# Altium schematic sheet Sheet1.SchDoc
size 431 x 279 mm; Date: Not shown in title block; ApprovedBy: Not shown in title block; CheckedBy: Not shown in title block; Author: Not shown in title block; CompanyName: Not shown in title block; Engineer: Not shown in title block; Organization: Not shown in title block; Address1: Not shown in title block; Address2: Not shown in title block; Address3: Not shown in title block; Address4: Not shown in title block; DocumentNumber: 1; Revision: Use project parameter SCH_Rev; SheetNumber: 2; SheetTotal: 3; PageSetup: Record=PageOptions¦CenterHorizontal=True¦CenterVertical=True¦PrintScale=1.00¦XCorrection=1.00¦YCorrection=1.00¦PrintKind=0¦BorderSize=5000000¦LeftOffset=0¦BottomOffset=0¦Orientation=2¦PaperLength=1000¦PaperWidth=1000¦Scale=100¦PaperSource=15¦PrintQuality=600¦MediaType=1¦DitherType=10¦PaperKind=Letter¦PrintScaleMode=1
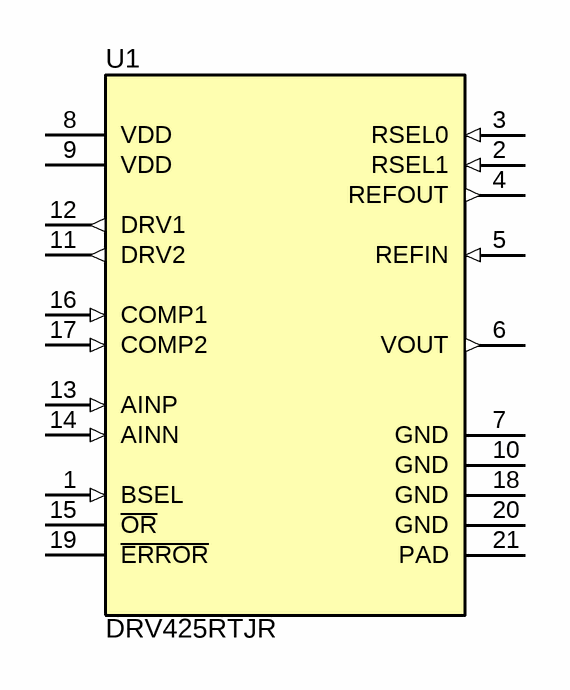
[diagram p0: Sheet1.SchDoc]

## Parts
U1  DRV425RTJR  [RTJ20_no_vias]

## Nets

Not connected (* = marked no-connect by the designer): U1 1(BSEL) 2(RSEL1) 3(RSEL0) 4(REFOUT) 5(REFIN) 6(VOUT) 7(GND) 8(VDD) 9(VDD) 10(GND) 11(DRV2) 12(DRV1) 13(AINP) 14(AINN) 15(~{OR}) 16(COMP1) 17(COMP2) 18(GND) 19(~{ERROR}) 20(GND) 21(PAD)

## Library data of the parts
U1 = DRV425RTJR: Fully Integrated Precision Fluxgate Magnetic Field Sensor and readout, RTJ0020G (WQFN-20); Alternate PartNumber: DRV425RTJRT; Manufacturer: Texas Instruments; SymbolCreator: Altium; CompType: IC; U/M: EA; SizeArea_mm2: 16; SizeAreaWB_mm2: 25; SizeX_mm: 4; SizeZ_mm: 0.8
